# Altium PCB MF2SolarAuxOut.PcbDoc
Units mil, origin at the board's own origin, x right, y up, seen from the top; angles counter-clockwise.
Board outline 1968.5 x 4527.56 mil, 2 copper layers (Top Layer, Bottom Layer), stack 61.2 mil thick; 53 components, 33 nets, 139 pads, 47 vias.
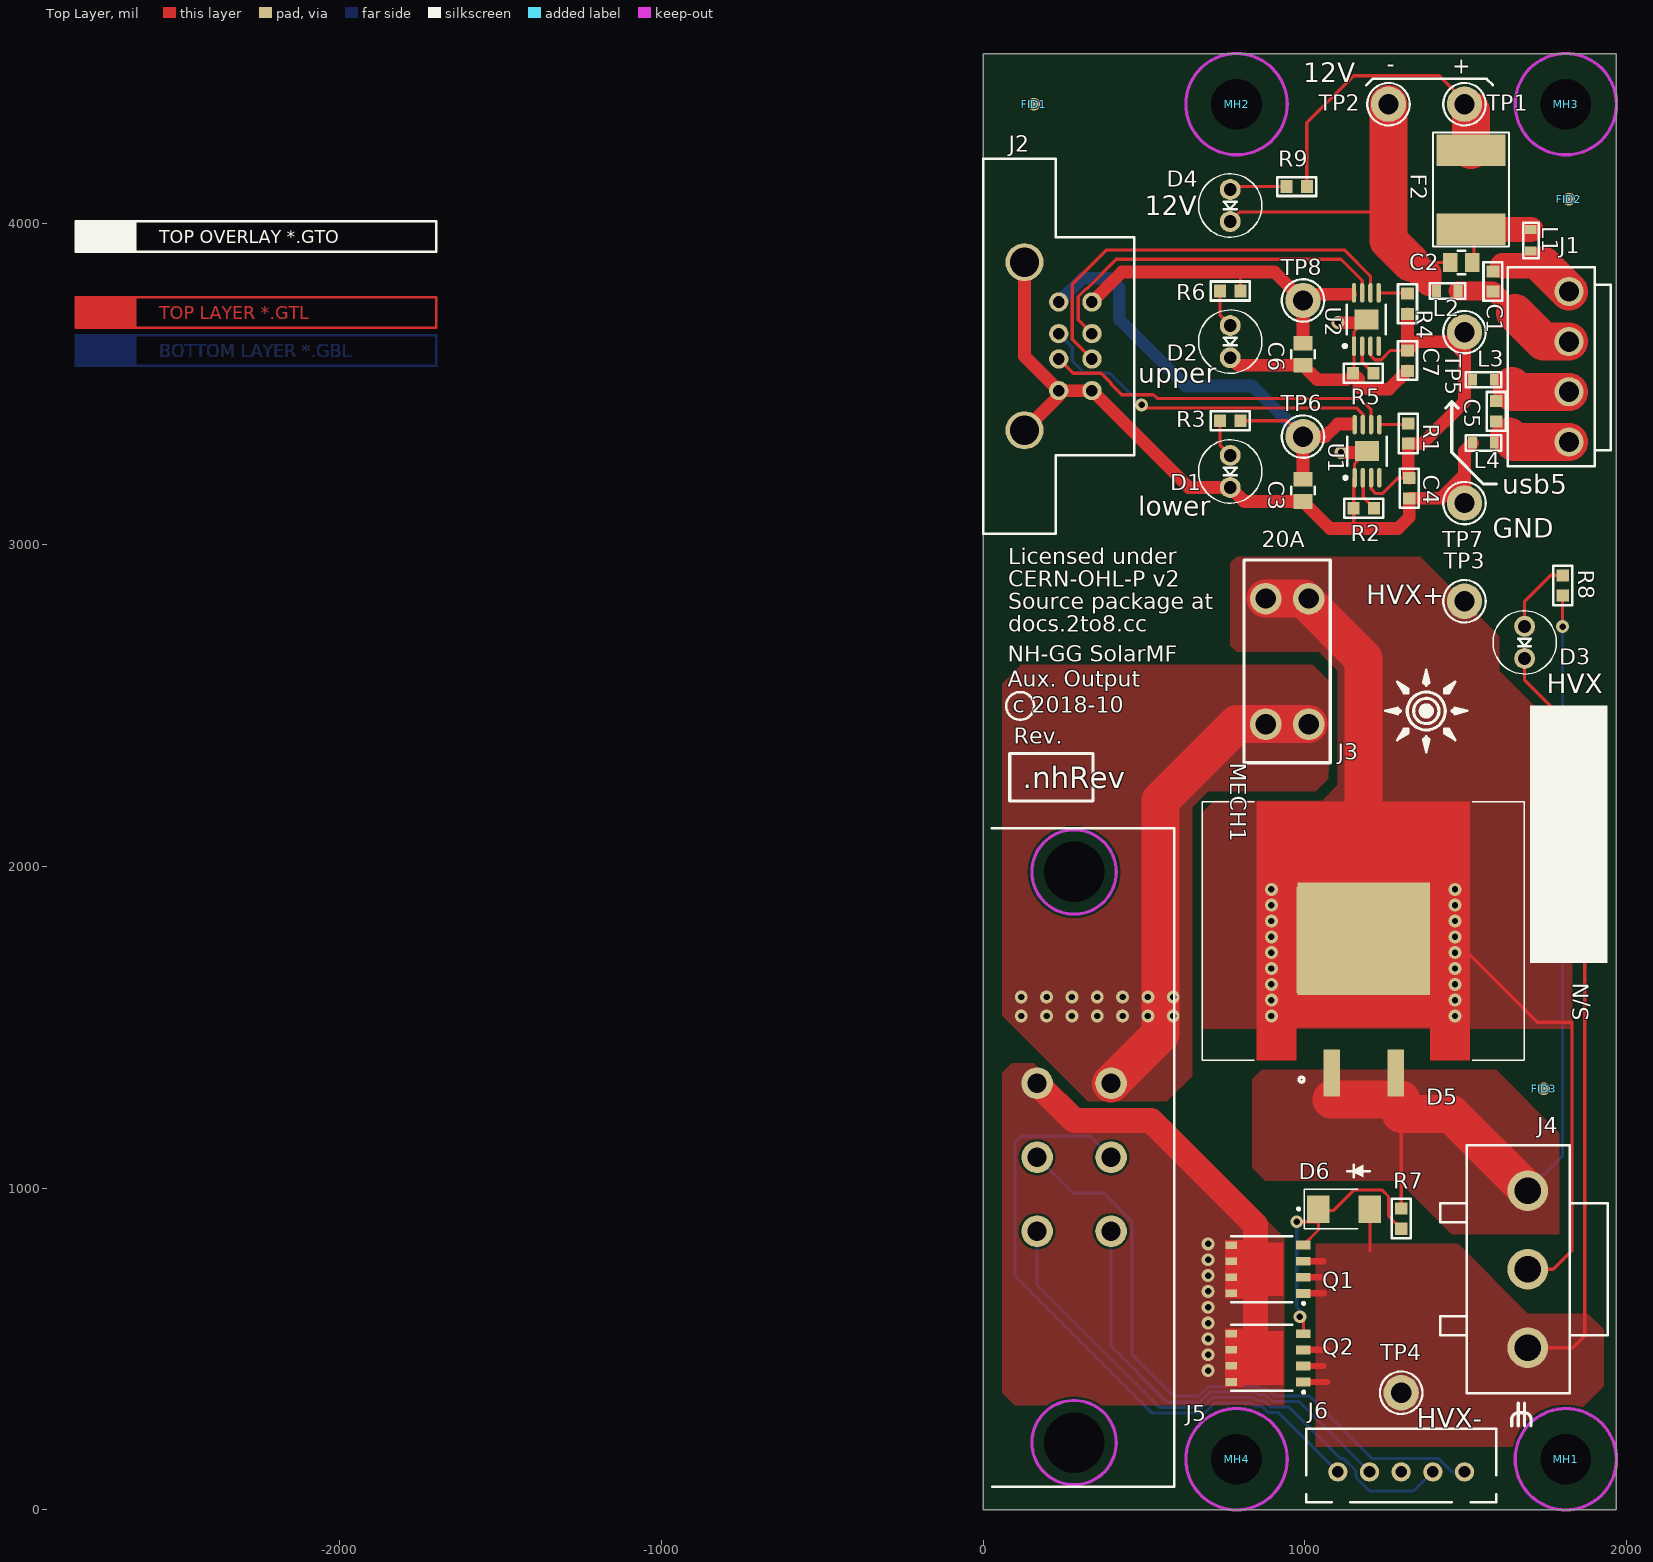
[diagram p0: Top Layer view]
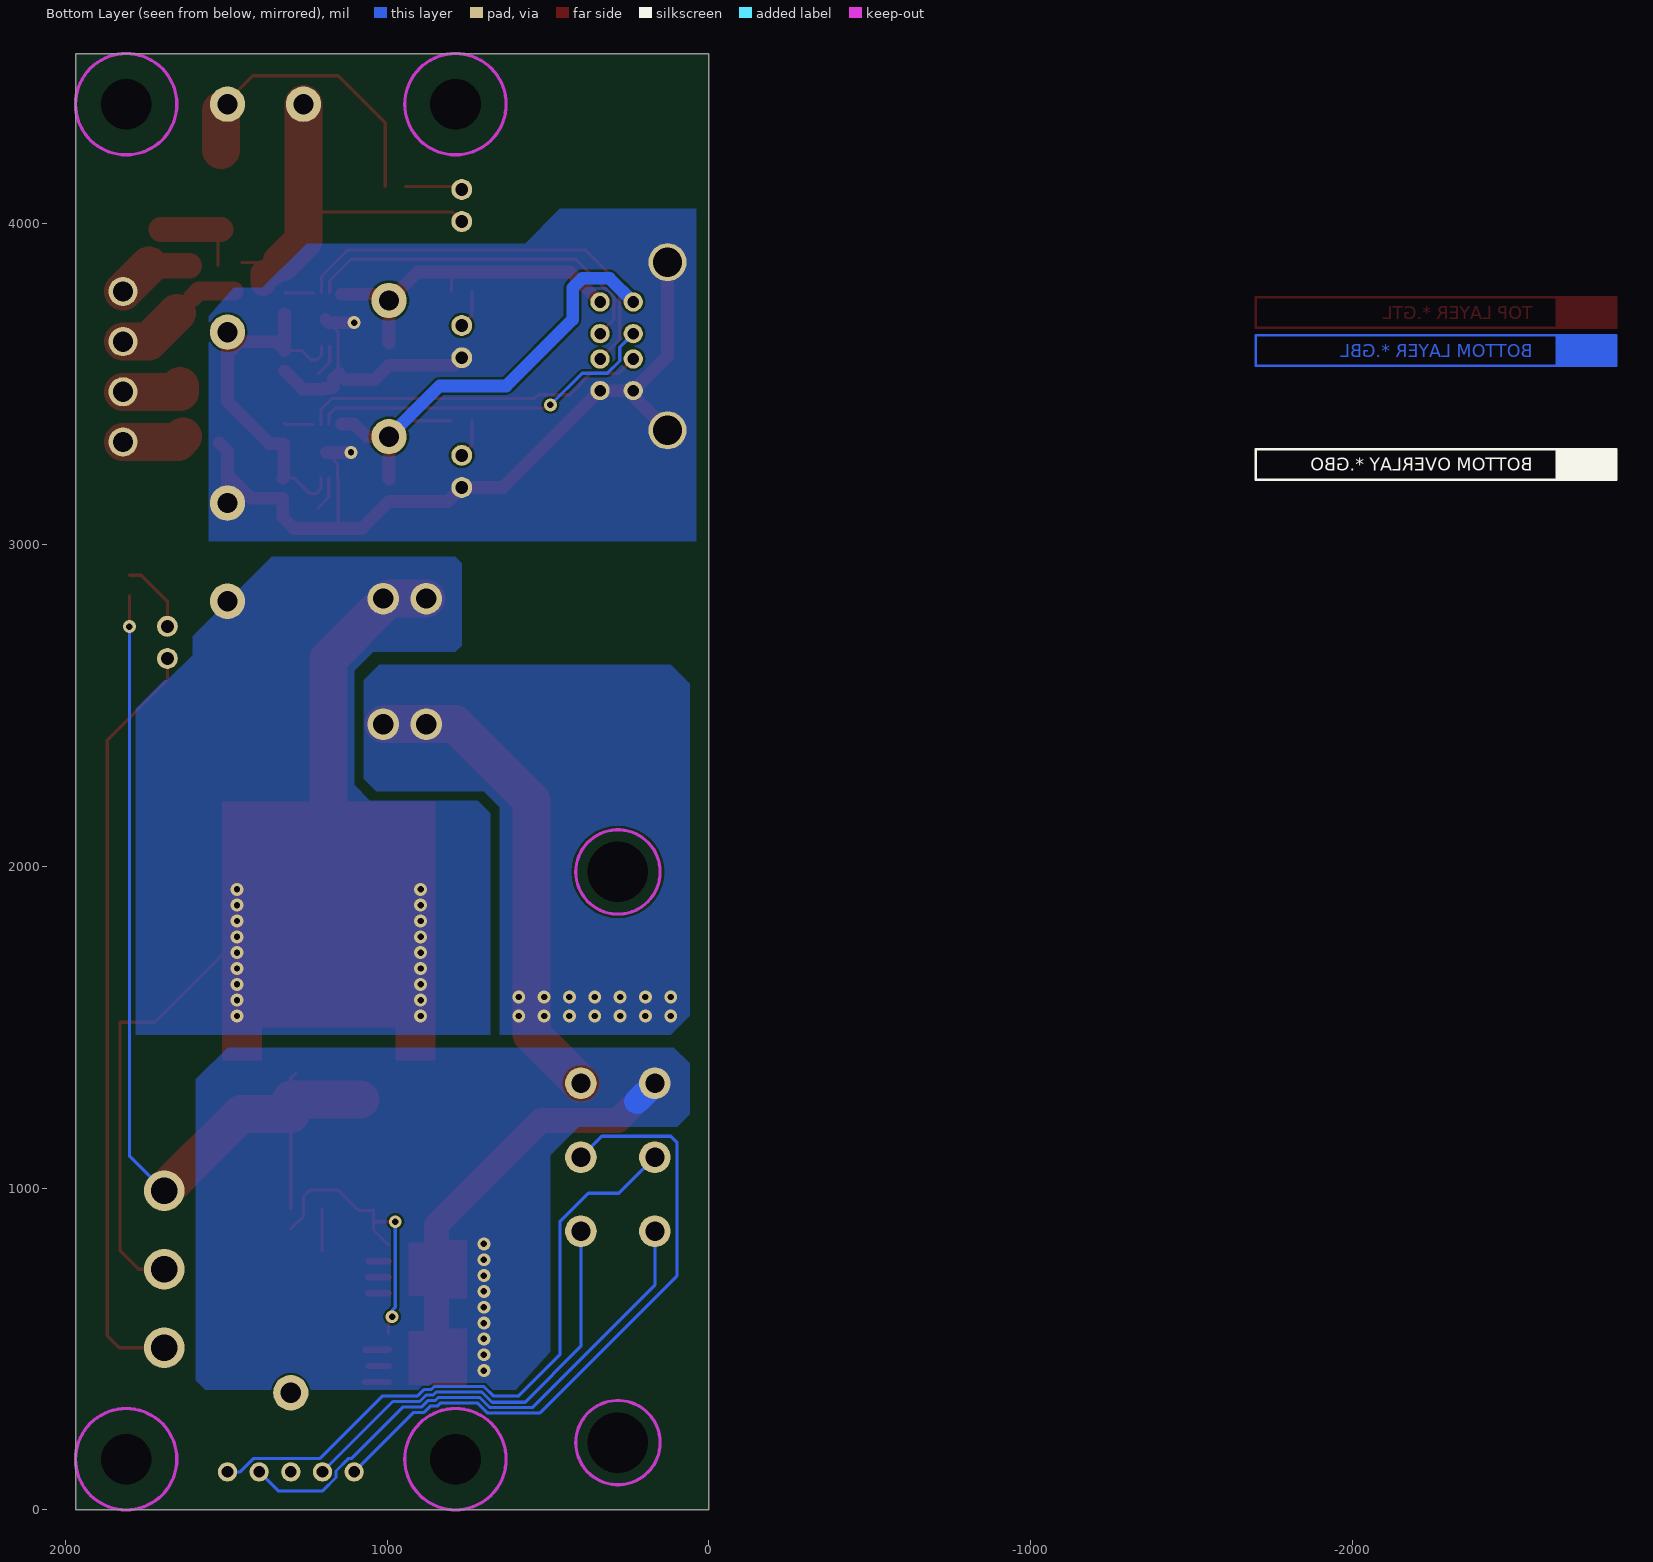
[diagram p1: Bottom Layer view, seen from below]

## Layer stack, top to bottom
Top Solder: solder mask 0.4, Solder Resist, Dk 3.5
Top Layer: signal copper 1.4
Dielectric 1: dielectric 58.4, FR-4, Dk 4.8
Bottom Layer: signal copper 1.4
Bottom Solder: solder mask 0.4, Solder Resist, Dk 3.5

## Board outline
0,0 1968.5,0 1968.5,4527.56 0,4527.56

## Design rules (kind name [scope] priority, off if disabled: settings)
Clearance [All] p1: gap=7 ignorepadtopadclearanceinfootprint=FALSE except(0: Arc-Hole Track-Hole SMDPad-Hole THPad-Hole Via-Hole Fill-Hole Poly-Hole Region-Hole Text-Hole)
DiffPairsRouting [All] p1: maxlimit=10 minlimit=10 mostfreqgap=10 substack1={34F67F1D-141E-4845-8DA9-B0992B6EDB11} toplayer_{34f67f1d-141e-4845-8da9-b0992b6edb11}_minwidth=15 toplayer_{34f67f1d-141e-4845-8da9-b0992b6edb11}_maxwidth=15 toplayer_{34f67f1d-141e-4845-8da9-b0992b6edb11}_prefwidth=15 bottomlayer_{34f67f1d-141e-4845-8da9-b0992b6edb11}_minwidth=15 bottomlayer_{34f67f1d-141e-4845-8da9-b0992b6edb11}_maxwidth=15 bottomlayer_{34f67f1d-141e-4845-8da9-b0992b6edb11}_prefwidth=15 toplayer_minwidth=15 toplayer_maxwidth=15 toplayer_prefwidth=15 bottomlayer_minwidth=15 bottomlayer_maxwidth=15 bottomlayer_prefwidth=15 maxuncoupledlength=500
HoleSize [All] p1: absolutevalues=TRUE maxlimit=150 minlimit=16 maxpercent=80.000 minpercent=20.000
PolygonConnect PolygonConnectGND [InNet('GND_AUX2')] p1: connectstyle=Direct reliefconductorwidth=10 reliefentries=4 polygonreliefangle="90 Angle" airgapwidth=10
PolygonConnect [All] p2: connectstyle=Direct reliefconductorwidth=10 reliefentries=4 polygonreliefangle="90 Angle" airgapwidth=10
RoutingVias [All] p1: holewidth=20 width=40 viastyle="Through Hole" minholewidth=20 minwidth=40 maxholewidth=20 maxwidth=40
SolderMaskExpansion [All] p1: expansion=4 istentingtop=FALSE
Width [All] p1: maxlimit=118.11 minlimit=7 preferedwidth=10 substack1={34F67F1D-141E-4845-8DA9-B0992B6EDB11}
28 further rules are at their usual default settings.

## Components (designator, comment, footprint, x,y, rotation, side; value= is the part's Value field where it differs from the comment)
C1 "50V C0G 0603" CAPC1608X09N[0603] 1584.65,3818.9 r270 top value=1E-9
C2 "16V X5R 0805" CAPC2012X145 1486.22,3877.95 r180 top value=2.2E-5
C3 "16V X5R 0805" CAPC2012X145 994.09,3169.29 r270 top value=2.2E-5
C4 "50V X7R 0603" CAPC1608X09N[0603] 1323.82,3176.18 r270 top value=1E-7
C5 "50V C0G 0603" CAPC1608X09N[0603] 1594.49,3415.35 r270 top value=1E-9
C6 "16V X5R 0805" CAPC2012X145 994.09,3592.52 r270 top value=2.2E-5
C7 "50V X7R 0603" CAPC1608X09N[0603] 1318.9,3572.83 r270 top value=1E-7
D1 "GRN" LED-5MM-GREEN 767.72,3228.35 r270 top
D2 "GRN" LED-5MM-GREEN 767.72,3631.89 r270 top
D3 "GRN" LED-5MM-GREEN 1683.07,2696.85 r270 top
D4 "GRN" LED-5MM-GREEN 767.72,4055.12 r270 top
D5 "30V 40A" D2PAK_2_ANODE_NOSILK 1182.68,1618.4 r90 top
D6 "8.2V 1W" DO-214AC 1122.05,935.04 r0 top
F2 "15V 3A" FUSC7351X12N[2920] 1515.75,4104.33 r90 top
FID1 "fiducial" FIDUCIAL_1_3 157.48,4370.08 r0 top
FID2 "fiducial" FIDUCIAL_1_3 1820.87,4074.8 r90 top
FID3 "fiducial" FIDUCIAL_1_3 1742.13,1309.06 r90 top
J1 "1x4 3.96mm" AMP_1-1123723-4 1820.87,3553.8 r270 top locked
J2 "USB A" AMPH_MUSB-C111-00 126.38,3617.52 r270 top locked
J3 "MINI" KEYSTONE_3568 944.88,2637.8 r270 top
J4 "JST VL" JST_B03P-VL 1692.91,748.03 r270 top locked
J5 "MX150L" MOLEX_0194270018 282.32,1096.14 r270 top locked
J6 "1x5 2.5mm" JST_B5B-XH-A(LF)(SN) 1299.21,118.11 r0 top locked
L1 "26 ohm 6A" FER1608X100[0603] 1702.76,3946.85 r270 top value=26
L2 "26 ohm 6A" FER1608X100[0603] 1442.91,3789.37 r0 top value=26
L3 "26 ohm 6A" FER1608X100[0603] 1555.12,3513.78 r0 top value=26
L4 "26 ohm 6A" FER1608X100[0603] 1555.12,3316.93 r0 top value=26
MECH1 "SMT" AAVID_7109DG 1181.1,1771.65 r90 top
MH1 "mounting hole" MOUNT_HOLE_4MM_NOCOPPER 1811.02,157.48 r0 top
MH2 "mounting hole" MOUNT_HOLE_4MM_NOCOPPER 787.4,4370.08 r0 top
MH3 "mounting hole" MOUNT_HOLE_4MM_NOCOPPER 1811.02,4370.08 r0 top
MH4 "mounting hole" MOUNT_HOLE_4MM_NOCOPPER 787.4,157.48 r0 top
Q1 "N-CH 40V 100A" SOT669_LFPAK56 866.14,748.03 r180 top
Q2 "N-CH 40V 100A" SOT669_LFPAK56 866.14,472.44 r180 top
R1 "1/10W 0603 1%" RESC1608X05AN[0603] 1320.87,3346.46 r90 top value=30100
R2 "1/10W 0603 1%" RESC1608X05AN[0603] 1183.07,3114.17 r180 top value=30100
R3 "1/10W 0603 1%" RESC1608X05AN[0603] 767.72,3385.83 r180 top value=1000
R4 "1/10W 0603 1%" RESC1608X05AN[0603] 1318.9,3750 r90 top value=30100
R5 "1/10W 0603 1%" RESC1608X05AN[0603] 1181.1,3533.46 r180 top value=30100
R6 "1/10W 0603 1%" RESC1608X05AN[0603] 767.72,3789.37 r180 top value=1000
R7 "1/10W 0603 1%" RESC1608X05AN[0603] 1299.21,905.51 r270 top value=1000
R8 "1/10W 0603 1%" RESC1608X05AN[0603] 1801.18,2874.02 r90 top value=2740
R9 "1/10W 0603 1%" RESC1608X05AN[0603] 974.41,4114.17 r180 top value=2740
TP1 "TP RED" KEYSTONE_5010 1496.06,4370.08 r0 top
TP2 "TP BLK" KEYSTONE_5011 1259.84,4370.08 r0 top
TP3 "TP RED" KEYSTONE_5010 1496.06,2824.8 r0 top
TP4 "TP BLK" KEYSTONE_5011 1299.21,364.17 r0 top
TP5 "TP RED" KEYSTONE_5010 1496.06,3661.42 r180 top
TP6 "TP RED" KEYSTONE_5010 994.1,3336.61 r180 top
TP7 "TP BLK" KEYSTONE_5011 1496.06,3129.92 r180 top
TP8 "TP RED" KEYSTONE_5010 994.09,3759.84 r180 top
U1 "TPS2511" TSOP65P490X110_HS-9N 1192.91,3291.34 r90 top
U2 "TPS2511" TSOP65P490X110_HS-9N 1190.94,3700.79 r90 top

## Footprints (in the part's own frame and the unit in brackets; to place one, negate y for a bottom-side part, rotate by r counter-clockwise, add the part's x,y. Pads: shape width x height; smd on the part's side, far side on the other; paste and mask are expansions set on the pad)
AAVID_7109DG [mm] "SMT heatsink for D2PAK packages"
  rect 8.38x10.5 smd: 1(0,0)
  Top Layer region: -9.5,-5.3 -9.5,-8.4 10.9,-8.4 10.9,8.4 -9.5,8.4 -9.5,5.3 -6.9,5.3 -6.9,-5.3
  silkscreen extent -9.5,-12.7 10.9,12.7, body extent -9.2,-12.6 10.3,12.6, height 11.5
AMP_1-1123723-4 [mm] "0.156\" (3.96mm) pitch header with latch"
  round 2.3 hole 1.6: 1(-5.944,0) 2(-1.984,0) 3(1.976,0) 4(5.936,0)
  silkscreen extent -7.87,-4.83 7.87,3.3, body extent -7.89,-4.8 7.89,3.7, height 10.75
AMPH_MUSB-C111-00 [mm] "Stacked dual right angle USB A Connector"
  round 1.524 hole 0.92: 1(-3.5,2.75) 2(-1,2.75) 3(1,2.75) 4(3.5,2.75) 5(-3.5,5.37) 6(-1,5.37) 7(1,5.37) 8(3.5,5.37)
  round 3 hole 2.3: 9(-6.635,0.04) 10(6.635,0.04)
  silkscreen extent -14.8,-3.2 14.8,8.7, body extent -15.25,-10.8 15.25,8.4, height 19.5
CAPC1608X09N[0603] [mm]
  rect 0.95x1 smd: 1(-0.8,0) 2(0.8,0)
  silkscreen extent -1.53,-0.75 1.53,0.75, body extent -0.85,-0.45 0.85,0.45, height 0.9
CAPC2012X145 [mm]
  rect 1.16x1.47 smd: 1(-0.875,0) 2(0.875,0)
  silkscreen extent -0.3,-0.92 0.3,0.92, body extent -1,-0.63 1,0.63, height 1.45
D2PAK_2_ANODE_NOSILK [mm] "DIODE SCHOTTKY D2PAK without silkscreen so can use heatsink"
  rect 3.7x1.3 smd mask+0.05: A1(-6.607,2.54) A2(-6.607,-2.54)
  rect 8.9x10.49 smd mask+0.05: K(4,0)
  silkscreen extent -7.33,4.7 -6.93,5.1, body extent -3,-5 7.4,5, height 4.6
DO-214AC [mil] "DIODE SCHOTTKY 5A 30V SMA"
  rect 70x85 smd: A(80,0) K(-80,0)
  silkscreen extent -146,-61 42,62, body extent -91,-57 91,57, height 96
FER1608X100[0603] [mm]
  rect 0.71x0.91 smd: 1(-0.85,0) 2(0.85,0)
  silkscreen extent -1.4,-0.6 1.4,0.6, body extent -0.8,-0.4 0.8,0.4, height 1
FIDUCIAL_1_3 [mm]
  round 1 smd paste-0.5 mask+1: 0(0,0)
FUSC7351X12N[2920] [mm] "Chip Fuse, 2-Leads, Body 7.36x5.12mm, IPC Medium Density"
  rect 2.5x5.45 smd: 1(-3.125,0) 2(3.125,0)
  silkscreen extent -4.5,-3 4.5,3, body extent -3.99,-2.72 3.99,2.72, height 1.25
JST_B03P-VL [mm] "6.2mm pitch header with latch"
  round 3.2 hole 2.1: 1(-6.2,0) 2(0,0) 3(6.2,0)
  silkscreen extent -9.8,-6.9 9.8,6.3, body extent -9.8,-6.9 9.8,6.3, height 16.5
JST_B5B-XH-A(LF)(SN) [mil]
  round 60 hole 36.22: 1(196.85,0) 2(98.43,0) 3(0,0) 4(-98.43,0) 5(-196.85,0)
  silkscreen extent -295,-94 295,134, body extent -293,-93 293,133, height 276
KEYSTONE_3568 [mm] "Fuseholder, MINI ATC, MINI ATO"
  round 2.5 hole 1.6: 1(-4.96,-1.7) 1(-4.96,1.7) 2(4.96,-1.7) 2(4.96,1.7)
  silkscreen extent -8,-3.4 8,3.4, body extent -8,-3.35 8,3.38, height 7.46
KEYSTONE_5010 [mil] "TEST POINT PC MULTIPURPOSE RED"
  round 110 / inner round 85 / far side round 110 hole 63: 1(0,0)
  silkscreen extent -66,-66 66,66, body extent -62,-62 63,63, height 320
KEYSTONE_5011 [mil] "TEST POINT PC MULTIPURPOSE BLK"
  round 110 / inner round 85 / far side round 110 hole 63: 1(0,0)
  silkscreen extent -66,-66 66,66, body extent -62,-62 63,63, height 320
LED-5MM-GREEN [mil]
  round 65 hole 40: A(-50,0) K(50,0)
  silkscreen extent -98,-98 98,98, body extent -105,-105 105,105, height 370
MOLEX_0194270018 [mm] "Sealed right angle 18A connector"
  round 0 hole 4.78: 0(-22.53,0) 0(22.53,0)
  round 2.5 hole 1.52: 1(-5.842,2.921) 2(0,2.921) 3(5.842,2.921) 4(-5.842,-2.921) 5(0,-2.921) 6(5.842,-2.921)
  silkscreen extent -26,-6.5 26,7.92, body extent -26,-31.72 26.08,7.93, height 32.3
MOUNT_HOLE_4MM_NOCOPPER [mm] "hole sized for a 4mm screw"
  round 1 hole 4 unplated: 1(0,0)
RESC1608X05AN[0603] [mm]
  rect 0.95x1 smd: 1(-0.8,0) 2(0.8,0)
  silkscreen extent -1.55,-0.75 1.55,0.75, body extent -0.85,-0.45 0.85,0.45, height 0.5
SOT669_LFPAK56 [mm] "On Semi LFPAK56 transistor package, alpha pin names"
  rect 0.9x0.6 smd: D(2.425,1.905) D(2.425,-0.635) D(2.425,0.635) D(2.425,-1.905)
  rect 1.15x0.7 smd: G(-3.275,-1.905) S(-3.275,-0.635) S(-3.275,0.635) S(-3.275,1.905)
  Top Layer region: -1.7,-2.1 1.4,-2.1 1.4,-2.3 2.9,-2.3 2.9,2.3 1.4,2.3 1.4,2.1 -1.7,2.1
  silkscreen extent -3.4,-2.6 2.4,2.8, body extent -3.7,-2.6 2.8,2.6, height 1.1
TSOP65P490X110_HS-9N [mm] "TSOP, 8-Leads, Body 3.00x3.00mm, Pitch 0.65mm, Thermal Pad 1.89x1.57mm, IPC Medium Density"
  oval 1.55x0.35 smd: 1(-2.1,0.975) 2(-2.1,0.325) 3(-2.1,-0.325) 4(-2.1,-0.975) 5(2.1,-0.975) 6(2.1,-0.325) 7(2.1,0.325) 8(2.1,0.975)
  rect 1.57x1.89 smd: 9(0,0)
  silkscreen extent -2.22,-1.55 1.15,1.82, body extent -1.55,-1.55 1.55,1.55, height 1.1

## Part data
C1 C5: library part CAP-00053, "1000pF ±5% 50V Ceramic Capacitor C0G, NP0 0603 (1608 Metric)", manufacturer="Murata Electronics North America", manufacturer_pn=GRM1885C1H102JA01D, Supplier Part Number 1=490-1451-1-ND, value_text=1n
C2 C3 C6: library part CAP-00031, "22µF 16V Ceramic Capacitor X5R 0805 (2012 Metric) 0.079\" L x 0.049\" W (2.00mm x 1.25mm)", manufacturer="Murata Electronics North America", manufacturer_pn=GRM21BR61C226ME44L, Supplier Part Number 1=490-10747-1-ND, value_text=22u
C4 C7: library part CAP-00001, "0.10µF 50V Ceramic Capacitor X7R 0603 (1608 Metric) 0.063\" L x 0.031\" W (1.60mm x 0.80mm)", manufacturer="Murata Electronics North America", manufacturer_pn=GCM188R71H104KA57J, Supplier Part Number 1=490-8020-1-ND, value_text=0.1u
D1 D2 D3 D4: library part LED-00019, "LED Panel Indicator Green Diffused 60° 2.2V 25mA Round with Domed Top, 3mm (T-1) Wire Leads - 6in (152.40mm)", manufacturer="Lumex Opto/Components Inc.", manufacturer_pn=SSI-RM3091SUGD-150, Supplier Part Number 1=67-1688-ND
D5: library part DIO-00034, "Diode Schottky 30V 40A Surface Mount D2PAK", manufacturer="ON Semiconductor", manufacturer_pn=MBRB4030G, Supplier Part Number 1=MBRB4030GOS-ND
D6: library part DIO-00017, "Zener Diode 8.2V 1W ±5% Surface Mount SMA", manufacturer="Diodes Incorporated", manufacturer_pn=SMAZ8V2-13-F, Supplier Part Number 1=SMAZ8V2-FDICT-ND
F2: library part FUSE-00010, "Polymeric PTC Resettable Fuse 15V 3A Ih Surface Mount 2920 (7351 Metric), Concave", manufacturer="Littelfuse Inc.", manufacturer_pn=2920L300/15DR, Supplier Part Number 1=F2875CT-ND
FID1 FID2 FID3: library part NOBOM-00010, "Fiducial, 1mm dia, 3mm solder mask opening", manufacturer="New Horizons"
J1: library part CONN-00068, "4 Positions Header, Unshrouded Connector 0.156\" (3.96mm) Through Hole Tin (GRN)", manufacturer="TE Connectivity AMP Connectors", manufacturer_pn=6-1123723-4, Supplier Part Number 1=A116707-ND
J2: library part CONN-00127, "USB - A, Stacked USB 2.0 Receptacle Connector 8 Position Panel Mount, Through Hole, Right Angle", manufacturer="Amphenol Commercial Products", manufacturer_pn=MUSB-C111-30, Supplier Part Number 1=MUSB-C111-30-ND
J3: library part CONN-00117, "FUSE HOLDER BLADE 500V 20A PCB", manufacturer="Keystone Electronics", manufacturer_pn=3568, Supplier Part Number 1=36-3568-ND
J4: library part CONN-00119, "3 Positions Header Connector 0.244\" (6.20mm) Through Hole Tin", manufacturer="JST Sales America Inc.", manufacturer_pn=B03P-VL, Supplier Part Number 1=455-2362-ND
J5: library part CONN-00128, "6 Positions Header Connector 0.230in (5.84mm) Panel Mount, Through Hole, Right Angle Tin", manufacturer="Molex, LLC", manufacturer_pn=19427-0018, Supplier Part Number 1=WM17506-ND
J6: library part CONN-00116, "5 Positions Header Connector 0.098\" (2.50mm) Through Hole Tin", manufacturer="JST Sales America Inc.", manufacturer_pn=B5B-XH-A(LF)(SN), Supplier Part Number 1=455-2270-ND
L1 L2 L3 L4: library part FER-00008, "FERRITE BEAD 26 OHM 0603 1LN 7 mohm", manufacturer="TDK Corporation", manufacturer_pn=MPZ1608S260ATAH0, Supplier Part Number 1=445-172749-1-ND, value_text=26
MECH1: library part MECH-00028, "Heat Sink TO-263 (D²Pak) Copper 2W @ 30°C Top Mount", manufacturer="Aavid Thermalloy", manufacturer_pn=7109DG, Supplier Part Number 1=HS406-ND
MH1 MH2 MH3 MH4: library part NOBOM-00014, "Mounting hole, 4mm NPT", manufacturer="New Horizons"
Q1 Q2: library part FET-00015, "N-Channel 40V 100A (Tc) 167W (Tc) Surface Mount LFPAK56, Power-SO8", manufacturer="Nexperia USA Inc.", manufacturer_pn=BUK9Y3R5-40E,115, Supplier Part Number 1=1727-1811-1-ND
R1 R2 R4 R5: library part RES-00026, "RES SMD 30.1K OHM 1% 1/10W 0603", manufacturer="Panasonic Electronic Components", manufacturer_pn=ERJ-3EKF3012V, Supplier Part Number 1=P30.1KHCT-ND, value_text=30.1k
R3 R6 R7: library part RES-00113, "1 kOhms ±1% 0.1W, 1/10W Chip Resistor 0603 (1608 Metric) Automotive AEC-Q200 Thick Film", manufacturer="Panasonic Electronic Components", manufacturer_pn=ERJ-3EKF1001V, Supplier Part Number 1=P1.00KHCT-ND, value_text=1k
R8 R9: library part RES-00055, "RES SMD 2.74K OHM 1% 1/10W 0603", manufacturer="Panasonic Electronic Components", manufacturer_pn=ERJ-3EKF2741V, Supplier Part Number 1=P2.74KHCT-ND, value_text=2.74k
TP1 TP3 TP5 TP6 TP8: library part CONN-00027, "TEST POINT PC MULTI PURPOSE RED", manufacturer="Keystone Electronics", manufacturer_pn=5010, Supplier Part Number 1=36-5010-ND
TP2 TP4 TP7: library part CONN-00028, "TEST POINT PC MULTI PURPOSE BLK", manufacturer="Keystone Electronics", manufacturer_pn=5011, Supplier Part Number 1=36-5011-ND
U1 U2: library part ICPWR-00029, "USB Dedicated Charging Port (DCP), Power Switch PMIC 8-MSOP-PowerPad", manufacturer="Texas Instruments", manufacturer_pn=TPS2511DGNR, Supplier Part Number 1=296-30552-1-ND

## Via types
v1: diameter 40, hole 20, Top Layer to Bottom Layer, 41 vias
v2: diameter 40, hole 20, Top Layer to Bottom Layer, tented both sides, 6 vias

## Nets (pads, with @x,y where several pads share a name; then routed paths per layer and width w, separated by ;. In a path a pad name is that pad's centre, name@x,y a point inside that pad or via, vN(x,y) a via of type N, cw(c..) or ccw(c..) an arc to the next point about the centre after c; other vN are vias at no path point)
5V_AUX2: C4.1 C7.1 L3.1 R1.1 R4.1 TP5.1 U1.3 U2.3 | length 1213.1
  Top Layer w9.84: U2.3 1203.74,3589.57 1217.63,3575.68 1237.12,3575.68 1265.78,3604.33 C7.1 ; U1.3 1205.71,3174.21 1220.47,3159.45 1240.16,3159.45 1288.38,3207.68 C4.1
  Top Layer w39.37: R4.1 C7.1 1346.46,3631.89 1456.69,3631.89 1496.06,3592.52 ; C4.1 1320.87,3210.63 R1.1 1366.14,3314.96 1496.06,3444.88 1496.06,3592.52 ; TP5.1 1496.06,3592.52
12V_AUX1: C2.1 F2.1 L1.1 | length 299.6
  Top Layer w9.84: F2.1 F2.1@1516.73,3980.31 ; C2.1@1525.59,3868.11 F2.1@1525.59,3980.31
  Top Layer w78.74: F2.1@1516.73,3980.31 1525.59,3980.31 L1.1
GND_AUX1: C2.2 D4.K L2.1 TP2.1 | length 1244.4
  Top Layer w7.87: 1352.25,3846.57 1383.64,3877.95 C2.2
  Top Layer w9.84: D4.K 798.03,4035.43 1259.84,4035.43
  Top Layer w78.74: 1328.74,3877.95 1328.74,3870.08 1352.25,3846.57 1384.95,3846.57 1384.95,3813.87
  Top Layer w118.11: TP2.1 1259.84,4035.43 1259.84,3946.85 1328.74,3877.95
GND_AUX2: C3.2 C4.2 C6.2 C7.2 D1.K D2.K J2.4 J2.8 J2.9 J2.10 L4.1 R2.2 R5.2 TP7.1 U1.1 U1.9 U2.1 U2.9 | length 3568.5
  Top Layer w9.84: R5.2 1152.56,3536.42 U2.1 1152.56,3662.4 U2.9@1181.1,3690.94 ; 1151.57,3051.18 R2.2 1151.57,3205.71 U1.1 1154.53,3252.95 1188.98,3287.4 U1.9
  Top Layer w39.37: J2.10 234.65,3462.99 J2.4 ; J2.9 127.95,3586.42 J2.4 ; D2.K 791.53,3558.07 C6.2 1038.39,3513.78 1129.92,3513.78 ; v2(1102.36,3690.94) 1181.1,3690.94 U2.9 ; v2(1112.2,3287.4) U1.9@1188.98,3287.4 ; R5.2 1167.21,3515.86 1167.21,3488.08 1181.86,3488.08 1182.84,3487.1 1195.98,3487.1 1198.82,3484.25 1261.81,3484.25 C7.2 ; TP7.1 1496.06,3218.5 ; L4.1 1496.06,3291.34 1496.06,3218.5 ; J2.4 J2.8 639.17,3178.35 D1.K 811.22,3134.84 C3.2 1077.76,3051.18 1151.57,3051.18 1289.37,3051.18 1323.82,3085.63 C4.2 1422.24,3144.68 1496.06,3218.5
HVX_3V3: J5.2 J6.5 | length 2030.5
  Bottom Layer w9.84: J5.2 332.05,1161.42 118.11,1161.42 98.43,1141.73 98.43,728.35 525.81,300.96 686.85,300.96 689.08,303.19 690.04,303.19 719.57,332.73 833.13,332.73 842.48,323.38 864.58,323.38 884.76,303.19 917.28,303.19 J6.5
HVX_A2P: J5.3 J6.4 | length 1349.3
  Bottom Layer w9.84: J5.3 397.32,508.19 570.87,334.65 672.9,334.65 675.13,336.88 676.09,336.88 705.62,366.41 847.09,366.41 856.43,357.06 878.53,357.06 898.72,336.88 982.02,336.88 J6.4
HVX_N1: D3.K D6.A J4.3 Q1.S Q2.S TP4.1 | length 2904.1
  Top Layer w9.84: 1202.05,805.83 D6.A ; D3.K 1683.07,2579.53 1870.08,2392.52 1870.08,541.34 1832.68,503.94 J4.3
  Top Layer w19.68: Q2.S@995.08,397.44 1069.09,397.44 ; Q2.S@995.08,447.44 1057.68,447.44 ; Q2.S@995.08,497.44 1067.52,497.44 ; Q1.S@995.08,673.03 1059.25,673.03 ; Q1.S@995.08,723.03 1058.46,723.03 ; Q1.S@995.08,773.03 1057.68,773.03
HVX_N2: J5.4 Q1.D Q2.D | length 1354.7
  Top Layer w78.74: J5.4 282.83,1210.63 521.65,1210.63 846.46,885.83 846.46,472.44
  Bottom Layer w78.74: J5.4 223.78,1269.69
  other v1: 698.82,433.07 698.82,482.28 698.82,531.5 698.82,580.71 698.82,629.92 698.82,679.13 698.82,728.35 698.82,777.56 698.82,826.77
HVX_P1: D5.A1 D5.A2 J4.1 R7.1 R8.1 | length 3018.3
  Top Layer w9.84: D5.A2 1299.21,1341.73 D5.A2@1299.21,1289.37 ; R7.1 1299.21,1230.32 1299.21,1275.43 ; v2(1801.18,2746.06) R8.1
  Top Layer w118.11: 1082.68,1275.43 1299.21,1275.43 ; 1299.21,1230.32 1454.72,1230.32 J4.1
  Bottom Layer w9.84: J4.1 1801.18,1100.39 v2(1801.18,2746.06)
HVX_P2: D5.K J3.1 J4.2 MECH1.1 TP3.1 | length 2879.1
  Top Layer w9.84: D5.K 1462.31,1775.88 1722.44,1515.75 1830.71,1515.75 1830.71,807.09 1771.65,748.03 J4.2
  Top Layer w118.11: J3.1@877.95,2833.07 995.67,2833.07 1182.68,2646.06 D5.K
  other v1: 895.67,1535.43 1466.54,1535.43 895.67,1584.65 1466.54,1584.65 895.67,1633.86 1466.54,1633.86 895.67,1683.07 1466.54,1683.07 895.67,1732.28 1466.54,1732.28 895.67,1781.5 1466.54,1781.5 895.67,1830.71 1466.54,1830.71 895.67,1879.92 1466.54,1879.92 895.67,1929.13 1466.54,1929.13
HVX_P2A: J5.6 J6.2 | length 1725.2
  Bottom Layer w9.84: J5.6 167.32,698.82 548.34,317.8 679.88,317.8 682.11,320.03 683.06,320.03 712.6,349.57 840.11,349.57 849.46,340.22 871.55,340.22 891.74,320.03 949.65,320.03 1109.65,160.03 1119.73,160.03 1158.87,120.89 1158.87,100.75 1200.56,59.06 1338.58,59.06 J6.2
HVX_P3: J3.2 J5.1 | length 1501.4
  Top Layer w118.11: J5.1 551.18,1480 551.18,2204.72 788.98,2442.52 877.95,2442.52 J3.2@1011.81,2442.52
  other v1: 118.11,1535.43 196.85,1535.43 275.59,1535.43 354.33,1535.43 433.07,1535.43 511.81,1535.43 590.55,1535.43 118.11,1594.49 196.85,1594.49 275.59,1594.49 354.33,1594.49 433.07,1594.49 511.81,1594.49 590.55,1594.49
HVX_SGND: J5.5 J6.1 | length 2000
  Bottom Layer w9.84: J5.5 279.21,984.25 374.02,984.25 462.6,895.67 462.6,482.28 590.55,354.33 669.72,354.33 698.64,383.25 854.06,383.25 863.41,373.91 885.5,373.91 905.08,354.33 1013.78,354.33 1208.08,160.03 1415,160.03 1456.92,118.11 J6.1
NetC1_1: C1.1 J1.1 L1.2 | length 240
  Top Layer w78.74: 1614.17,3868.11 1740.55,3868.11
  Top Layer w118.11: 1740.55,3868.11 J1.1
NetC1_2: C1.2 J1.2 L2.2 | length 340.1
  Top Layer w59.06: L2.2 1584.65,3789.37 1604.33,3769.69
  Top Layer w118.11: 1653.54,3720.47 1742.13,3631.89 J1.2
NetC3_1: C3.1 J2.1 R3.1 TP6.1 U1.8 | length 1563.4
  Top Layer w9.84: R3.1 944.88,3385.83 TP6.1
  Top Layer w39.37: C3.1 TP6.1 1062.99,3336.61 1102.36,3375.98 1141.73,3375.98
  Bottom Layer w39.37: J2.1 308.07,3828.74 393.7,3828.74 423.23,3799.21 423.23,3700.79 629.92,3494.09 836.61,3494.09 TP6.1
NetC5_1: C5.1 J1.3 L3.2 | length 195.3
  Top Layer w118.11: 1643.7,3494.09 1643.7,3475.99 J1.3
NetC5_2: C5.2 J1.4 L4.2 | length 193.9
  Top Layer w118.11: 1633.86,3336.61 1650.39,3320.08 J1.4
NetC6_1: C6.1 J2.5 R6.1 TP8.1 U2.8 | length 1080.1
  Top Layer w9.84: 797.24,3848.43 799.21,3846.46 R6.1
  Top Layer w39.37: J2.5 430.91,3848.43 797.24,3848.43 905.51,3848.43 TP8.1 ; C6.1 TP8.1 ; 1141.73,3779.53 1013.78,3779.53 TP8.1
NetD1_A: D1.A R3.2 | length 120.5
  Top Layer w9.84: R3.2 736.22,3309.84 D1.A
NetD2_A: D2.A R6.2 | length 120.5
  Top Layer w9.84: R6.2 736.22,3713.39 D2.A
NetD3_A: D3.A R8.2 | length 229.5
  Top Layer w9.84: D3.A 1683.07,2824.8 1763.78,2905.51 R8.2
NetD4_A: D4.A R9.2 | length 178.9
  Top Layer w9.84: D4.A 776.77,4114.17 R9.2
NetD6_K: D6.K Q1.G Q2.G R7.2 | length 906.9
  Top Layer w9.84: v2(974.41,895.67) D6.K@1042.05,895.67 ; Q2.G v2@995.08,584.84 ; Q1.G 1042.05,870 D6.K@1042.05,895.67 ; R7.2 1259.84,913.39 1259.84,974.41 1240.16,994.09 1151.58,994.09 1087.79,930.31 1046.77,930.31 D6.K D6.K@1042.05,895.67
  Bottom Layer w9.84: v2(974.41,895.67) 974.41,629.92 984.25,620.08 v2(984.25,600.39)
NetF2_2: F2.2 R9.1 TP1.1 | length 932.8
  Top Layer w9.84: R9.1 1005.91,4312.99 1151.57,4458.66 1417.32,4458.66 TP1.1@1496.06,4379.92 ; TP1.1 TP1.1@1515.75,4350.39
  Top Layer w118.11: F2.2 TP1.1@1515.75,4350.39
NetJ2_2: J2.2 U1.7 | length 1112.7
  Top Layer w9.84: v2(492.13,3435.04) 492.13,3425.2 1161.42,3425.2 1180.12,3406.5 U1.7
  Bottom Layer w9.84: J2.2 276.57,3614.97 276.57,3571.86 314.96,3533.46 393.7,3533.46 v2(492.13,3435.04)
NetJ2_3: J2.3 U1.6 | length 1084.5
  Top Layer w9.84: J2.3 279.33,3533.46 367.16,3533.46 396.56,3504.07 396.56,3501.08 430.68,3466.96 529.1,3466.96 540.57,3455.49 1170.5,3455.49 1205.71,3420.28 U1.6
NetJ2_6: J2.6 U2.7 | length 1129.3
  Top Layer w9.84: J2.6 295.28,3699.41 295.28,3772.08 320.43,3797.24 322.83,3797.24 413.39,3887.8 1112.2,3887.8 1178.15,3821.85 U2.7
NetJ2_7: J2.7 U2.6 | length 1314.9
  Top Layer w9.84: J2.7 276.57,3639.38 276.57,3810.03 383.86,3917.32 1122.05,3917.32 1203.74,3835.63 U2.6
NetR1_2: R1.2 U1.5 | length 91.2
  Top Layer w9.84: U1.5 1316.93,3374.02 R1.2
NetR2_1: R2.1 U1.2 | length 108.8
  Top Layer w9.84: U1.2 1181.1,3207.68 1181.1,3147.64 R2.1
NetR4_2: R4.2 U2.5 | length 90.4
  Top Layer w9.84: U2.5 1316.93,3783.47 R4.2
NetR5_1: R5.1 U2.2 | length 98.9
  Top Layer w9.84: U2.2 1178.15,3567.91 R5.1
pads on no net: FID1.0 FID2.0 FID3.0 J5.0 J6.3 MH1.1 MH2.1 MH3.1 MH4.1 U1.4 U2.4
copper on no net: | length 4868
  Top Layer w8: -2822,3675 -2822,3770 -1700,3770 -1700,3675 -2822,3675
  Bottom Layer w8: -2822,3557 -2822,3652 -1700,3652 -1700,3557 -2822,3557

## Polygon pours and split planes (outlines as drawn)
HVX_P3 on Bottom Layer "hvx_p3_bot" (solid, remove dead copper, pour order 16): 649.61,1476.38 649.61,2185.04 698.82,2234.25 1033.46,2234.25 1072.83,2273.62 1072.83,2578.74 1023.62,2627.95 118.11,2627.95 59.06,2568.9 59.06,1535.43 118.11,1476.38
HVX_P2 on Bottom Layer "hvx_22_bot" (solid, remove dead copper, pour order 14): 679.13,1476.38 1781.5,1476.38 1781.5,2490.16 1692.91,2578.74 1683.07,2578.74 1604.33,2657.48 1604.33,2716.54 1358.27,2962.6 787.4,2962.6 767.72,2942.91 767.72,2687.01 787.4,2667.32 1043.31,2667.32 1102.36,2608.27 1102.36,2253.94 1053.15,2204.72 718.5,2204.72 679.13,2165.35
HVX_N2 on Bottom Layer "hvx_n2_bot" (solid, remove dead copper, pour order 12): 600.39,374.02 1564.96,374.02 1594.49,403.54 1594.49,1338.58 1496.06,1437.01 108.27,1437.01 59.05,1387.8 59.06,1230.32 98.43,1190.94 403.54,1190.94 492.13,1102.36 492.13,492.13
GND_AUX2 on Bottom Layer "usb_gnd_bot" (solid, remove dead copper, pour order 0): 1555.12,3011.81 1555.12,3700.79 1555.12,3710.63 1476.38,3799.21 1387.8,3799.21 1250,3937.01 570.87,3937.01 462.6,4045.28 39.37,4045.28 39.37,3011.81
HVX_P3 on Top Layer "hvx_p3_top" (solid, remove dead copper, pour order 6): 1072.83,2273.62 1033.46,2234.25 698.82,2234.25 649.61,2185.04 649.61,1348.43 570.87,1269.69 324.8,1269.69 59.06,1535.43 59.06,2568.9 118.11,2627.95 1023.62,2627.95 1072.83,2578.74 1082.68,2578.74
HVX_N2 on Top Layer "hvx_n2_top" (solid, remove dead copper, pour order 10): 935.04,324.8 935.04,846.46 541.34,1240.16 305.12,1240.16 157.48,1387.8 88.58,1387.8 59.06,1358.27 59.06,364.17 98.43,324.8
HVX_N1 on Top Layer "hvx_n1_top" (solid, remove dead copper, pour order 8): 1033.46,826.77 1476.38,826.77 1692.91,610.24 1879.92,610.24 1929.13,561.02 1929.13,383.86 1742.13,196.85 1033.46,196.85
HVX_P2 on Top Layer "hvx_p2_top" (solid, remove dead copper, pour order 4): 679.13,1496.06 1830.71,1496.06 1830.71,2381.89 1604.33,2608.27 1604.33,2716.54 1358.27,2962.6 787.4,2962.6 767.72,2942.91 767.72,2687.01 787.4,2667.32 1043.31,2667.32 1102.36,2608.27 1102.36,2253.94 1053.15,2204.72 718.5,2204.72 679.13,2165.35
HVX_P1 on Top Layer "hvx_p1_top" (solid, remove dead copper, pour order 2): 1791.34,856.3 1791.34,1171.26 1594.49,1368.11 866.14,1368.11 836.61,1338.58 836.61,1062.99 875.98,1023.62 1289.37,1023.62 1456.69,856.3

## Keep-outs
Keep-Out Layer:
  circle w10: c282.32,209.13 r131.09
  circle w10: c282.32,1983.15 r131.15
  circle w10: c787.4,4370.08 r157.48
  circle w10: c1811.02,4370.08 r157.48
  circle w10: c1811.02,157.48 r157.48
  circle w10: c787.4,157.48 r157.48

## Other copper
Top Layer:
  rectangle: -2822,3675 -2632,3770
  text "TOP LAYER *.GTL" at -2562,3702 h40
Bottom Layer:
  rectangle: -2822,3557 -2632,3652
  text "BOTTOM LAYER *.GBL" at -2562,3584 h40

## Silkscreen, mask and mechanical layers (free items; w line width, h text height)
Top Overlay:
  circle w10: c1377.25,2483.69 r59.06
  circle w10: c1377.25,2483.69 r39.37
  circle w23.62: c1377.25,2483.69 r11.81
  circle w7.87: c114.73,2499.3 r43.31
  rectangle: 1700,1700 1940.94,2500
  rectangle: -2822,3911 -2632,4006
  region: 1141.73,1053.15 1181.1,1033.46 1181.1,1072.83
  lines w7.87: 1131.89,1053.15 1200.79,1053.15 ; 1151.57,1033.46 1151.57,1072.83 ; 1190.94,4429.13 1210.63,4448.82 1564.96,4448.82 1584.65,4429.13 ; 1432.93,2539.37 1446.85,2539.37 ; 1432.93,2539.37 1432.93,2553.29 ; 1432.93,2539.37 1446.85,2539.37 ; 1432.93,2539.37 1432.93,2553.29 ; 1432.93,2553.29 1467.73,2574.17 ; 1432.93,2553.29 1467.73,2574.17 ; 1446.85,2539.37 1467.73,2574.17 ; 1446.85,2539.37 1467.73,2574.17 ; 1249.3,2483.69 1288.67,2493.53 1298.51,2483.69 1288.67,2473.85 1249.3,2483.69 ; 1286.78,2393.22 1307.66,2428.01 1321.58,2428.01 1321.58,2414.1 1286.78,2393.22 ; 1286.78,2574.17 1321.58,2553.29 1321.58,2539.37 1307.66,2539.37 1286.78,2574.17 ; 1367.41,2395.11 1377.25,2355.74 1387.1,2395.11 1377.25,2404.95 1367.41,2395.11 ; 1367.41,2572.28 1377.25,2562.43 1387.1,2572.28 1377.25,2611.65 1367.41,2572.28 ; 1432.93,2414.1 1467.73,2393.22 1446.85,2428.01 1432.93,2428.01 1432.93,2414.1 ; 1455.99,2483.69 1465.84,2493.53 1505.21,2483.69 1465.84,2473.85 1455.99,2483.69
  lines w8: -2822,3911 -2822,4006 -1700,4006 -1700,3911 -2822,3911
  lines w10: 1437.01,3425.2 1456.69,3444.88 ; 1476.38,3425.2 1456.69,3444.88 ; 1594.49,3188.98 1555.12,3188.98 1456.69,3287.4 1456.69,3444.88 ; 1643,261.72 1643,281.72 cw(c1663,281.72) 1663,301.72 1683,301.72 cw(c1683,281.72) 1703,281.72 1703,261.72 ; 1663,261.72 1663,331.72 ; 1683,261.72 1683,331.72 ; 82.53,2204.02 82.53,2351.66 341.11,2351.66 341.11,2204.02 82.53,2204.02
  lines w15.75: 1268.99,2483.69 1288.67,2483.69 ; 1300.7,2407.14 1314.62,2421.05 ; 1300.7,2560.25 1314.62,2546.33 ; 1377.25,2375.42 1377.25,2395.11 ; 1377.25,2572.28 1377.25,2591.96 ; 1439.89,2421.05 1453.81,2407.14 ; 1465.84,2483.69 1485.52,2483.69 ; 1439.89,2546.33 1453.81,2560.25 1439.89,2546.33
  text "-" at 1279.53,4507.87 h50 r180
  text "+" at 1515.75,4507.87 h50 r180
  text "12V" at 994.09,4438.98 h60.63
  text "12V" at 501.97,4025.59 h60
  text "TOP OVERLAY *.GTO" at -2562,3938 h40
  text "upper" at 482.28,3503.94 h60
  text "usb5" at 1614.17,3159.45 h60.63
  text "lower" at 482.28,3090.55 h60
  text "GND" at 1584.65,3021.65 h60.63
  text "20A" at 866.14,2992.13 h50
  text "Licensed under" at 78.33,2940 h50
  text "CERN-OHL-P v2" at 78.33,2870 h50
  text "HVX+" at 1190.94,2814.96 h60
  text "Source package at" at 78.33,2800 h50
  text "docs.2to8.cc" at 78.33,2730 h50
  text "NH-GG SolarMF" at 75.36,2637.1 h50
  text "Aux. Output" at 75.36,2558.36 h50
  text "HVX" at 1751.97,2539.37 h60
  text "c 2018-10" at 91.58,2478.83 h50
  text "Rev." at 95.05,2381.19 h50
  text ".nhRev" at 122.53,2243.08 h66.93
  text "S/N" at 1882.2,1520.58 h50 r90
  text "HVX-" at 1348.43,255.91 h60
Bottom Overlay:
  rectangle: -2822,3203 -2632,3298
  lines w8: -2822,3203 -1700,3203 -1700,3298 -2822,3298 -2822,3203
  text "BOTTOM OVERLAY *.GBO" at -2562,3230 h40
Top Paste:
  rectangle: -2822,4029 -2632,4124
  region: 1456.69,2145.67 1289.37,2145.67 1289.37,2007.87 1456.69,2007.87
  rectangle: 905.51,2007.87 1072.83,2145.67
  rectangle: 98.43,1584.65 610.24,1604.33
  rectangle: 98.43,1525.59 610.24,1545.28
  rectangle: 679.13,413.39 718.5,846.46
  rectangle: 1446.85,1515.75 1486.22,1948.82
  rectangle: 875.98,1515.75 915.35,1948.82
  lines w8: -2822,4029 -1700,4029 -1700,4124 -2822,4124 -2822,4029
  text "TOP PASTE *.GTP" at -2562,4056 h40
Bottom Paste:
  rectangle: -2822,3321 -2632,3416
  lines w8: -2822,3321 -2822,3416 -1700,3416 -1700,3321 -2822,3321
  text "BOTTOM PASTE *.GBP" at -2562,3348 h40
Top Solder:
  rectangle: -2822,3793 -2632,3888
  rectangle: 88.58,1505.91 620.08,1624.02
  rectangle: 669.29,403.54 728.35,856.3
  lines w8: -2822,3793 -2822,3888 -1700,3888 -1700,3793 -2822,3793
  text "TOP SOLDER MASK *.GTS" at -2562,3820 h40
Bottom Solder:
  rectangle: -2822,3439 -2632,3534
  rectangle: 1437.01,1505.91 1496.06,1958.66
  rectangle: 866.14,1505.91 925.2,1958.66
  rectangle: 88.58,1505.91 620.08,1624.02
  rectangle: 669.29,403.54 728.35,856.3
  lines w8: -2822,3439 -2822,3534 -1700,3534 -1700,3439 -2822,3439
  text "BOTTOM SOLDER MASK *.GBS" at -2562,3466 h40
1 Fab Drawing:
  lines w5: -6580,-3400 -6580,7600 9120,7600 9120,-3400 -6580,-3400
  lines w10: 4618.38,-3031.5 8868.38,-3031.5 ; 4618.38,-2531.5 8868.38,-2531.5 ; 4618.38,-2031.5 8868.38,-2031.5
  text "NEW HORIZONS, GHL" at 4723.38,-2401.5 h250
  text "PROJECT" at 4711.1,-2631.5 h60
  text "REV" at 7416.02,-2631.5 h60
  text "'.nhRev'" at 7386.02,-2906.5 h280
  text "'.nhProjName'" at 4740.98,-2915.2 h260
  text "FABRICATION DRAWING" at 6193.38,-3186.5 h100
2 Board Outline:
  rectangle: -2822,3085 -2632,3180
  lines w7.87: 0,0 1968.5,0 1968.5,4527.56 0,4527.56 0,0
  lines w8: -2822,3085 -1700,3085 -1700,3180 -2822,3180 -2822,3085
  text "BOARD OUTLINE *.GM2" at -2562,3112 h40
4 Gerber All:
  lines w8: -2900,3000 -1600,3000 -1600,4434 -2900,4434 -2900,3000
  lines w10: -2632,4214 -1862,4214
  text "LAYER USAGE" at -2632,4242 h80
5 Assembly Top:
  lines w5: -6580,-3400 9120,-3400 9120,7600 -6580,7600 -6580,-3400
  lines w10: 4618.38,-3031.5 8868.38,-3031.5 ; 4618.38,-2531.5 8868.38,-2531.5 ; 4618.38,-2031.5 8868.38,-2031.5
  text "NEW HORIZONS, GHL" at 4723.38,-2401.5 h250
  text "PROJECT" at 4711.1,-2631.5 h60
  text "REV" at 7416.02,-2631.5 h60
  text "PRIMARY SIDE" at -727.76,-2706.54 h300
  text "'.nhRev'" at 7386.02,-2906.5 h280
  text "'.nhProjName'" at 4740.98,-2915.2 h260
  text "ASSEMBLY DRAWING, TOP" at 6193.38,-3186.5 h100
6 Assembly Bot:
  lines w5: -6580,-3400 9120,-3400 9120,7600 -6580,7600 -6580,-3400
  lines w10: -6428.39,-3031.5 -2178.39,-3031.5 ; -6428.39,-2531.5 -2178.39,-2531.5 ; -6428.39,-2031.5 -2178.39,-2031.5
  text "NEW HORIZONS, GHL" at -2283.39,-2401.5 h250
  text "REV" at -4976.03,-2631.5 h60
  text "Project" at -2271.11,-2631.5 h60
  text "SECONDARY SIDE" at 3082.24,-2701.54 h300
  text "'.nhRev'" at -4946.03,-2906.5 h280
  text "'.nhProjName'" at -2300.99,-2915.2 h260
  text "ASSEMBLY DRAWING, BOTTOM" at -3753.39,-3186.5 h100
7 Fab Notes:
  drawing of 346 lines, arcs and shapes, not listed
  text "Layer" at -3022.5,6877.5 h60
  text "Name" at -2612.59,6877.5 h60
  text "Material" at -1682.84,6877.5 h60
  text "Thickness" at -823.08,6877.5 h60
  text "Constant" at -173.24,6877.5 h60
  text "Board Layer Stack" at 396.62,6877.5 h60
  text "Board Layer Stack" at 1516.3,6877.5 h60
  text "MATERIAL:  FR4" at -6067.8,6857.29 h100
  text "2 LAYERS OF 1OZ COPPER" at -6067.8,6757.29 h100
  text "Top Overlay" at -2612.59,6757.5 h60
  text "SILVER IMMERSION" at -6067.8,6657.29 h100
  text "Top Solder" at -2612.59,6637.5 h60
  text "Solder Resist" at -1682.84,6637.5 h60
  text "0.40mil" at -823.08,6637.5 h60
  text "3.5" at -173.24,6637.5 h60
  text "1" at -3022.5,6517.5 h60
  text "Top Layer" at -2612.59,6517.5 h60
  text "1.40mil" at -823.08,6517.5 h60
  text "FINISHED BOARD THICKNESS = 0.062\" / 1.57mm" at -6067.8,6457.29 h100
  text "Dielectric 1" at -2612.59,6397.5 h60
  text "FR-4" at -1682.84,6397.5 h60
  text "58.40mil" at -823.08,6397.5 h60
  text "4.8" at -173.24,6397.5 h60
  text "UL 94V-0" at -6067.8,6357.29 h100
  text "2" at -3022.5,6277.5 h60
  text "Bottom Layer" at -2612.59,6277.5 h60
  text "1.40mil" at -823.08,6277.5 h60
  text "GREEN SOLDERMASK OVER BARE COPPER, BOTH SIDES" at -6067.8,6157.29 h100
  text "Bottom Solder" at -2612.59,6157.5 h60
  text "Solder Resist" at -1682.84,6157.5 h60
  text "0.40mil" at -823.08,6157.5 h60
  text "3.5" at -173.24,6157.5 h60
  text "WHITE SILKSCREEN OVER SOLDERMASK (TOP ONLY)" at -6067.8,6057.29 h100
  text "Bottom Overlay" at -2612.59,6037.5 h60
  text "DIMENSIONS IN MILS (0.001\")" at -6067.8,5857.29 h100
  text "NC DRILL FILE IS MF2SolarAuxOut.TXT" at -6067.8,5657.29 h100
  text "OTHER FILE EXTENSIONS ARE NOTED IN THE \"LAYER USAGE\" BLOCK IN THE Artwork.PDF." at -6067.8,5557.29 h100
  text "[115mm]" at 2540,2060 h60 r90
  text "[111mm]" at 2310,1970 h60 r90
  text "[4mm]" at 2070,710 h60 r90
  text "[20mm]" at 190,-160 h60
  text "[46mm]" at 710,-310 h60
  text "[50mm]" at 780,-500 h60
  text "NEW HORIZONS, GHL" at 4723.38,-2401.5 h250
  text "PROJECT" at 4711.1,-2631.5 h60
  text "REV" at 7416.02,-2631.5 h60
  text "'.nhEngName'" at 8105,-2650 h90
  text "'.nhEngPhone'" at 8105,-2750 h90
  text "'.nhEngEmail'" at 8105,-2850 h90
  text "'.nhRev'" at 7386.02,-2906.5 h280
  text "'.nhProjName'" at 4740.98,-2915.2 h260
  text "'.nhToday'" at 8105,-2950 h90
  text "FABRICATION NOTES" at 6191.77,-3186.5 h100
Drill Drawing:
  circle w10: c-5029.38,1795.83 r33.33
  circle w10: c-5029.38,1645.83 r20
  circle w10: c-5029.38,1645.83 r33.33
  lines w10: -5062.71,412.5 -5062.71,429.17 -5046.04,445.83 -5062.71,462.5 -5062.71,479.17 -5046.04,479.17 -5029.38,462.5 -5012.71,479.17 -4996.04,479.17 -4996.04,462.5 -5012.71,445.83 -4996.04,429.17 -4996.04,412.5 -5012.71,412.5 -5029.38,429.17 -5046.04,412.5 -5062.71,412.5 ; -5062.71,562.5 -4996.04,562.5 -4996.04,629.17 -5062.71,629.17 -5062.71,562.5 ; -5062.71,779.17 -4996.04,779.17 -5029.38,712.5 -5062.71,779.17 ; -5062.71,895.83 -5029.38,862.5 -4996.04,895.83 -5029.38,929.17 -5062.71,895.83 ; -5062.71,1012.5 -5029.38,1029.17 -4996.04,1012.5 -5012.71,1045.83 -4996.04,1079.17 -5029.38,1062.5 -5062.71,1079.17 -5046.04,1045.83 -5062.71,1012.5 ; -5062.71,1162.5 -4996.04,1162.5 -4996.04,1229.17 -5062.71,1229.17 -5062.71,1162.5 ; -5062.71,1329.17 -5046.04,1329.17 -5046.04,1312.5 -5012.71,1312.5 -5012.71,1329.17 -4996.04,1329.17 -4996.04,1362.5 -5012.71,1362.5 -5012.71,1379.17 -5046.04,1379.17 -5046.04,1362.5 -5062.71,1362.5 -5062.71,1329.17 ; -5062.71,1529.17 -4996.04,1529.17 -5029.38,1462.5 -5062.71,1529.17 ; -5049.38,1175.83 -5009.38,1175.83 -5009.38,1215.83 -5049.38,1215.83 -5049.38,1175.83 ; -5049.38,1515.83 -5009.38,1515.83 -5029.38,1475.83 -5049.38,1515.83
  lines w15: -5122.5,367.5 -1557.44,367.5 ; -5122.5,1867.5 -1557.44,1867.5 ; -4571.62,217.5 -4571.62,2017.5 ; -3991.78,217.5 -3991.78,2017.5 ; -2842.11,217.5 -2842.11,2017.5 ; -2336.24,217.5 -2336.24,2017.5 ; -5122.5,217.5 -1557.44,217.5 -1557.44,2017.5 -5122.5,2017.5 -5122.5,217.5
  text "Symbol" at -5032.5,1912.5 h72
  text "Count" at -4526.62,1912.5 h72
  text "Hole Size" at -3946.78,1912.5 h72
  text "Plated" at -2797.11,1912.5 h72
  text "Hole Type" at -2291.24,1912.5 h72
  text "2" at -4526.62,1762.5 h60
  text "2.300mm (90.55mil)" at -3946.78,1762.5 h60
  text "PTH" at -2797.11,1762.5 h60
  text "Round" at -2291.24,1762.5 h60
  text "2" at -4526.62,1612.5 h60
  text "4.780mm (188.19mil)" at -3946.78,1612.5 h60
  text "PTH" at -2797.11,1612.5 h60
  text "Round" at -2291.24,1612.5 h60
  text "3" at -4526.62,1462.5 h60
  text "2.100mm (82.68mil)" at -3946.78,1462.5 h60
  text "PTH" at -2797.11,1462.5 h60
  text "Round" at -2291.24,1462.5 h60
  text "4" at -4526.62,1312.5 h60
  text "4.000mm (157.48mil)" at -3946.78,1312.5 h60
  text "NPTH" at -2797.11,1312.5 h60
  text "Round" at -2291.24,1312.5 h60
  text "6" at -4526.62,1162.5 h60
  text "1.520mm (59.84mil)" at -3946.78,1162.5 h60
  text "PTH" at -2797.11,1162.5 h60
  text "Round" at -2291.24,1162.5 h60
  text "8" at -4526.62,1012.5 h60
  text "1.016mm (40.00mil)" at -3946.78,1012.5 h60
  text "PTH" at -2797.11,1012.5 h60
  text "Round" at -2291.24,1012.5 h60
  text "8" at -4526.62,862.5 h60
  text "1.600mm (62.99mil)" at -3946.78,862.5 h60
  text "PTH" at -2797.11,862.5 h60
  text "Round" at -2291.24,862.5 h60
  text "8" at -4526.62,712.5 h60
  text "1.600mm (63.00mil)" at -3946.78,712.5 h60
  text "PTH" at -2797.11,712.5 h60
  text "Round" at -2291.24,712.5 h60
  text "13" at -4526.62,562.5 h60
  text "0.920mm (36.22mil)" at -3946.78,562.5 h60
  text "PTH" at -2797.11,562.5 h60
  text "Round" at -2291.24,562.5 h60
  text "47" at -4526.62,412.5 h60
  text "0.508mm (20.00mil)" at -3946.78,412.5 h60
  text "PTH" at -2797.11,412.5 h60
  text "Round" at -2291.24,412.5 h60
  text "101 Total" at -4526.62,262.5 h60

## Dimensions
1968.5,0 to 1968.5,4527.56 on 7 Fab Notes
1968.5,0 to 1811.02,4370.08 on 7 Fab Notes
1968.5,0 to 1811.02,157.48 on 7 Fab Notes
0,0 to 1968.5,0 on 7 Fab Notes
0,0 to 1811.02,157.48 on 7 Fab Notes
0,0 to 787.4,157.48 on 7 Fab Notes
